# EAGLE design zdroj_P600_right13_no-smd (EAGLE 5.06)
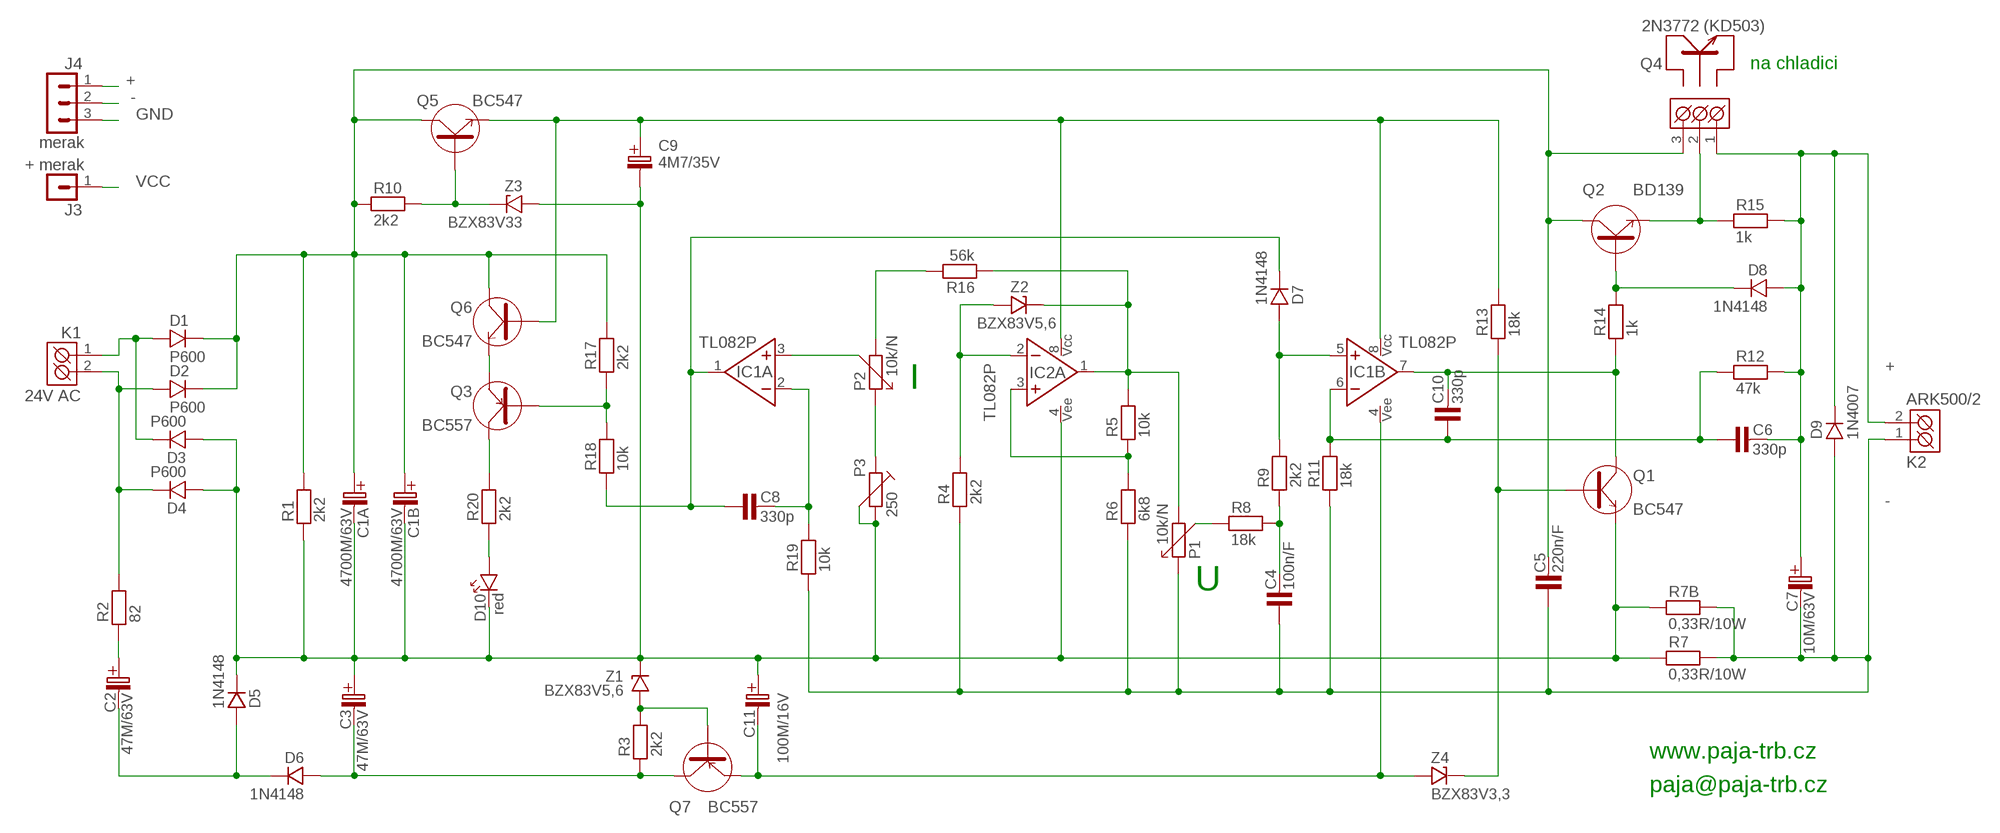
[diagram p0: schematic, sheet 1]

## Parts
C1A  4700M/63V  [C_EL12,5]
C1B  4700M/63V  [C_EL12,5]
C2  47M/63V  [C_EL_3,5]
C3  47M/63V  [C_EL_3,5]
C4  100n/F  100N-K/100  [RM5_3,2]
C5  220n/F  220N-K/63V  [RM5_3,2]
C6  330p  C-KERAMIK_2,5  [C-2,5]
C7  10M/63V  [C_EL_2]
C8  330p  C-KERAMIK_2,5  [C-2,5]
C9  4M7/35V  4M7/50V  [C_EL_2]
C10  330p  C-KERAMIK_2,5  [C-2,5]
C11  100M/16V  [C_EL_2,5]
D1  P600  D_P6  [P6]
D2  P600  D_P6  [P6]
D3  P600  D_P6  [P6]
D4  P600  D_P6  [P6]
D5  1N4148  1N4148_7,5  [DO35]
D6  1N4148  1N4148_7,5  [DO35]
D7  1N4148  1N4148_7,5  [DO35]
D8  1N4148  1N4148_7,5  [DO35]
D9  1N4007  1N4007_10  [DO41]
D10  red  LED_5  [LED_5]
IC1  TL082P  TL072  [DIL8]
IC2  TL082P  TL072  [DIL8]
J3  + merak  S1G1_JUMP  [S1G1_JUM]
J4  merak  S1G3_JUMP  [S1G3_JUM]
K1  24V AC  ARK500/2  [ARK500/2]
K2  ARK500/2  [ARK500/2]
P1  10k/N  PC16ML"  [PC16ML]
P2  10k/N  PC16ML"  [PC16ML]
P3  250  TRIMRPT6V  [PT6V]
Q1  BC547  BC546  [TO-92]
Q2  BD139  BD139_STOJ  [TO-126S]
Q3  BC557  BC556  [TO-92]
Q4  2N3772 (KD503)  ARK500/3  [ARK500/3]
Q5  BC547  BC546  [TO-92]
Q6  BC547  BC546  [TO-92]
Q7  BC557  BC556  [TO-92]
R1  2k2  W2_2K2  [R__2W]
R2  82  R_7,5  [R-7,5]
R3  2k2  R_7,5  [R-7,5]
R4  2k2  R_7,5  [R-7,5]
R5  10k  R_7,5  [R-7,5]
R6  6k8  R_7,5  [R-7,5]
R7  0,33R/10W  R__10W  [R-_10W]
R7B  0,33R/10W  R__10W  [R-_10W]
R8  18k  R_7,5  [R-7,5]
R9  2k2  R_7,5  [R-7,5]
R10  2k2  R_7,5  [R-7,5]
R11  18k  R_7,5  [R-7,5]
R12  47k  R_7,5  [R-7,5]
R13  18k  R_7,5  [R-7,5]
R14  1k  R_7,5  [R-7,5]
R15  1k  R_7,5  [R-7,5]
R16  56k  R_7,5  [R-7,5]
R17  2k2  R_7,5  [R-7,5]
R18  10k  R_7,5  [R-7,5]
R19  10k  R_7,5  [R-7,5]
R20  2k2  R_7,5  [R-7,5]
Z1  BZX83V5,6  D-ZENEROVA_0,5W_BZX83V  [DO35]
Z2  BZX83V5,6  D-ZENEROVA_0,5W_BZX83V  [DO35]
Z3  BZX83V33  D-ZENEROVA_0,5W_BZX83V  [DO35]
Z4  BZX83V3,3  D-ZENEROVA_2W_BZY  [DO41]

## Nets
+: C6.2 C7.C+(C_EL+) D8.A D9.K J4.1 K2.2(K2) Q4.1(K1) R12.2 R15.2
-: C4.1 C5.1 C7.C-(C_EL-) D9.A J4.2 K2.1(K1) P1.1 R4.1 R6.1 R7.2 R7B.2 R11.1 R19.1
GND: C1A.C-(C_EL-) C1B.C-(C_EL-) C3.C+(C_EL+) C9.C-(C_EL-) C11.C+(C_EL+) D3.A D4.A D5.K D10.K IC2.4(NS:VEE) J4.3 P3.2 P3.3 Q1.3(E) R1.1 R7.1 R7B.1 Z1.K Z3.A
N$2: Q3.1(C) R20.2
N$3: C2.C+(C_EL+) R2.1
N$5: C2.C-(C_EL-) D5.A D6.K
N$6: C3.C-(C_EL-) D6.A Q7.1(C) R3.1
N$8: C11.C-(C_EL-) IC1.4(NS:VEE) Q7.3(E) Z4.A
N$9: C8.1 D7.K IC1.1(A:VYSTUP) R18.1
N$10: IC1.3(A:NEIN+) P2.3
N$11: Q5.2(B) R10.2 Z3.K
N$12: D10.A R20.1
N$13: Q3.3(E) Q6.3(E)
N$14: P1.3 R8.1
N$15: Q3.2(B) R17.1 R18.2
N$17: C9.C+(C_EL+) IC1.8(NS:VCC) IC2.8(NS:VCC) Q5.3(E) Q6.2(B) R13.2
N$18: C8.2 IC1.2(A:IN-) R19.2
N$19: P2.1 P3.1
N$22: IC2.2(A:IN-) R4.2 Z2.A
N$23: IC2.3(A:NEIN+) R5.1 R6.2
N$24: IC2.1(A:VYSTUP) P1.2 R5.2 R16.1 Z2.K
N$25: P2.2 R16.2
N$27: C4.2 R8.2 R9.1
N$28: D7.A IC1.5(B:NEIN+) R9.2
N$29: C6.1 C10.1 IC1.6(B:IN-) R11.2 R12.1
N$31: C10.2 IC1.7(B:VYSTUP) Q1.1(C) R14.1
N$32: Q1.2(B) R13.1 Z4.K
N$33: Q2.1(E) Q4.2(K2) R15.1
N$36: D8.K Q2.3(B) R14.2
STRID1: D1.A D3.K K1.1(K1)
STRID2: D2.A D4.K K1.2(K2) R2.2
VCC: C1A.C+(C_EL+) C1B.C+(C_EL+) C5.2 D1.K D2.K J3.1 Q2.2(C) Q4.3(K3) Q5.1(C) Q6.1(C) R1.2 R10.1 R17.2
Z1: Q7.2(B) R3.2 Z1.A
Unconnected: IC2.5(B:NEIN+) IC2.6(B:IN-) IC2.7(B:VYSTUP)

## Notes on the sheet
- na chladici
- I
- U
- www.paja-trb.cz
- paja@paja-trb.cz

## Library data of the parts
C1A C1B = #PaJa_C-el_2:4700M/63V
C2 C3 = #PaJa_C-el_2:47M/63V
C4 = #PaJa_C-folie:100N-K/100
C5 = #PaJa_C-folie:220N-K/63V
C6 C8 C10 = #PaJa_22:C-KERAMIK: Kondenzator - keramicky
C7 = #PaJa_C-el_2:10M/63V
C9 = #PaJa_C-el_2:4M7/50V
C11 = #PaJa_C-el_2:100M/16V
D1-D4 = #PaJa_23_e56:D: Dioda - univerzální
D5-D8 = #PaJa_23_e56:1N4148: Univerzalni dioda - 0,15A, 75V
D9 = #PaJa_23_e56:1N4007: Usmernovaci dioda - 1A, 1000V
D10 = #PaJa_23_e56:LED: LED - jednobarevna
IC1 IC2 = #PaJa_23_e56:TL072: OZ - JFET - 2x
J3 = #PaJa_23_e56:S1G1_JUMP: Radove konektory - koliky - 1x
J4 = #PaJa_23_e56:S1G3_JUMP: Radove konektory - koliky - 3x
K1 K2 = #PaJa_23_e56:ARK500/2: Svorkovnice - roztec 5mm - dvojita
P1 P2 = #PaJa_23_e56:PC16ML: Potenciometr - plastovy - mono - 100R az 5M
P3 = #PaJa_22:TRIMR: Trimr
Q1 Q5 Q6 = #PaJa_23_e56:BC546: Tranzistor NPN - Univerzalni NF - Ic=0,1A
Q2 = #PaJa_23_e56:BD139: Tranzistor NPN - Vykonovy - Ic=1,5A
Q3 Q7 = #PaJa_23_e56:BC556: Tranzistor PNP - Univerzalni NF - Ic=0,1A
Q4 = #PaJa_23_e56:ARK500/3: Svorkovnice - roztec 5mm - trojita
R1 = #PaJa_R:W2_2K2
R2 R3 R7 R7B R9-R12 R14 R15 R17 R18 = #PaJa_23_e56:R: Rezistor
R4-R6 R8 R13 R16 R19 R20 = #PaJa_22:R: Rezistor
Z1-Z4 = #PaJa_23_e56:D-ZENEROVA: Zenerova dioda

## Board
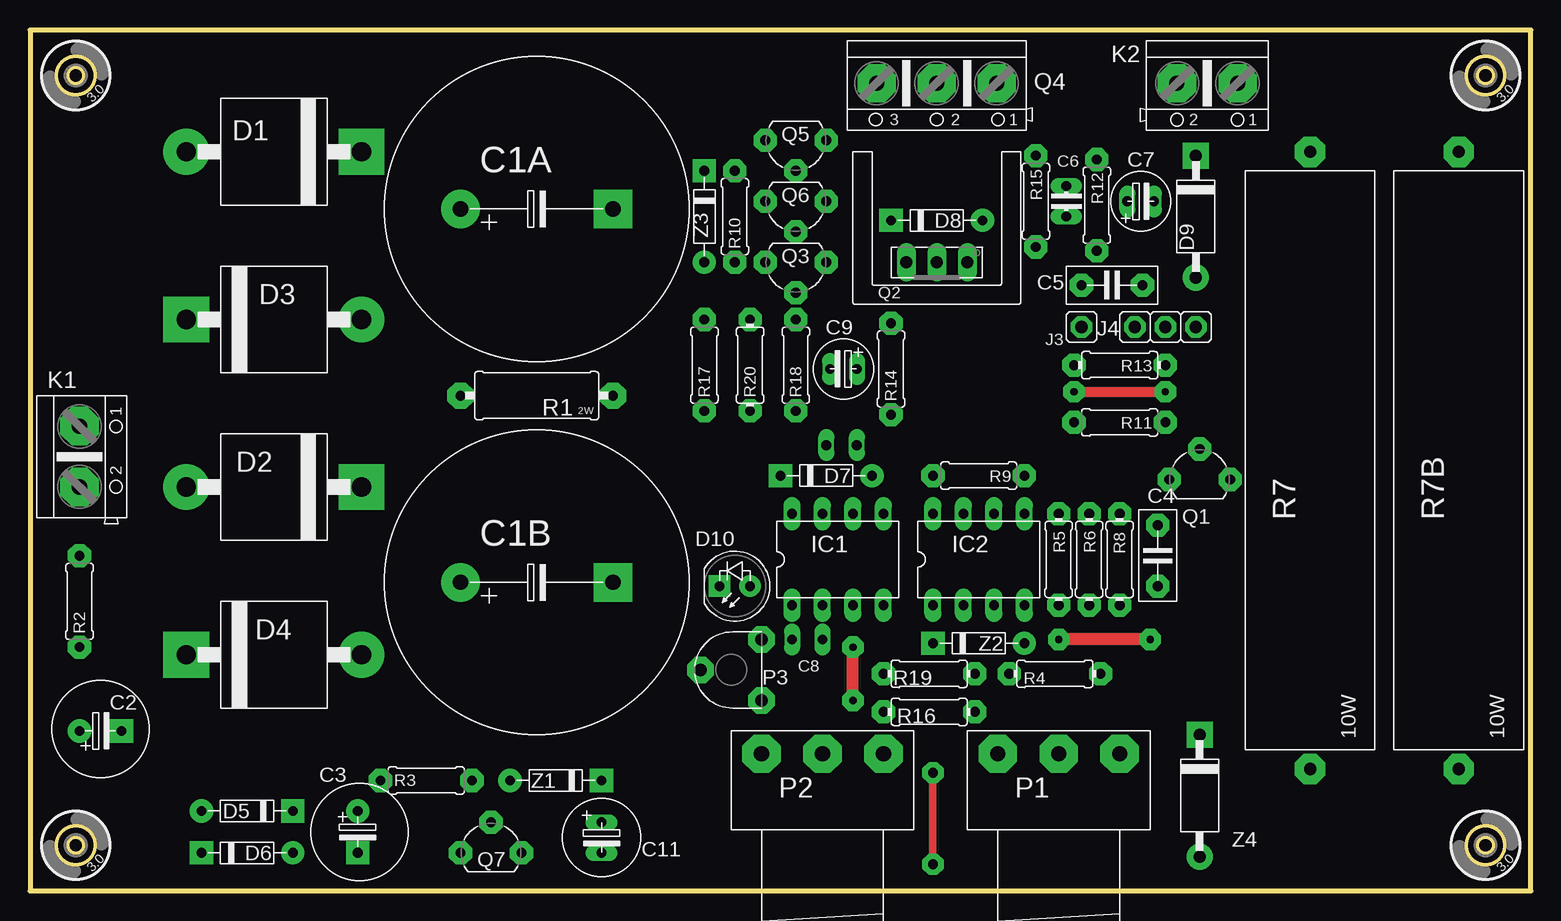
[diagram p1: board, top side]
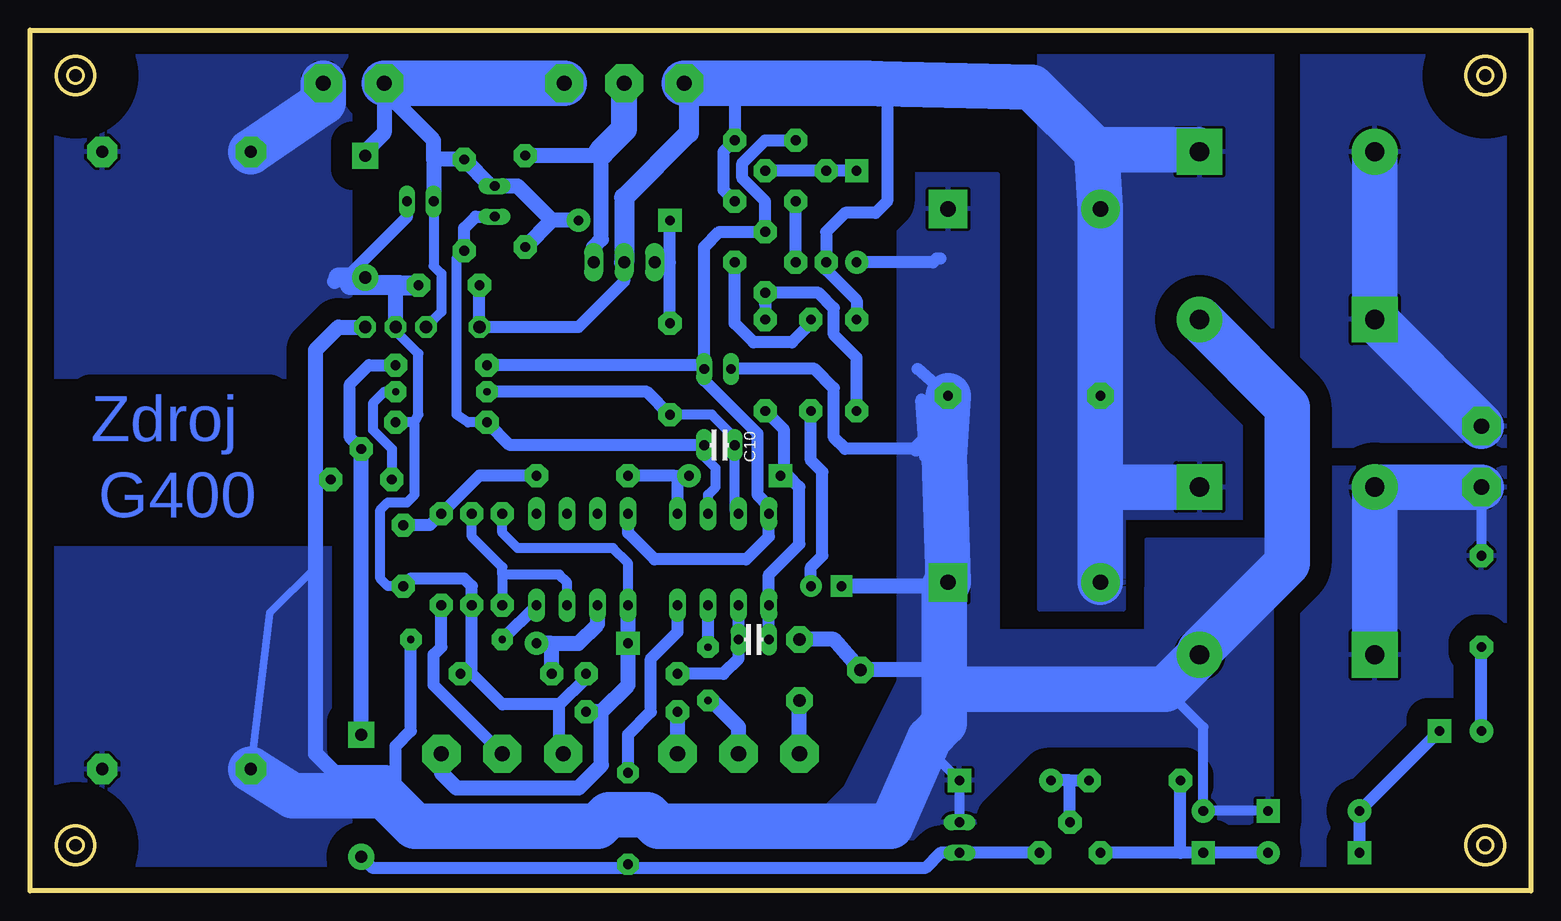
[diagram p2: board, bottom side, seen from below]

Size 125.08 x 71.75 mm. Coordinates in mm from the lower left corner, seen from the top.
Outline: 0,0 125.08,0 125.08,71.75 0,71.75 0,0
Copper layers (1*16): Top 0.035mm / dielectric 1.5mm / Bottom 0.035mm
Design rules "default": minimum track width 10mil, minimum drill 24mil, track to track 8mil, track to pad 8mil, pad to pad 8mil, via to via 8mil, smd to smd 8mil, copper to edge 40mil, drill to drill 8mil, minimum pad ring 10mil, minimum via ring 8mil, stop-mask expansion 4mil, vias tented up to drill 0mil, thermal gap 10mil
bRestrict: 2 lines

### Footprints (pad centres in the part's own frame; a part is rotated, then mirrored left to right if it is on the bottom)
C_EL12,5 = drill 1.27 pad 3.2 round: C+ -6.35,0 | drill 1.27 pad 3.2 square: C- 6.35,0
C_EL_3,5 = drill 0.813 pad 1.93 round: C+ 0,0 | drill 0.813 pad 1.93 square: C- 3.493,0
RM5_3,2 = drill 0.813 pad 1.93 octagon: 1 -2.54,0; 2 2.54,0
C-2,5 = drill 0.813 pad 1.27 long: 1 -1.27,0; 2 1.27,0
C_EL_2 = drill 0.813 pad 1.27 long: C+ 0,0; C- 2.223,0
C_EL_2,5 = drill 0.813 pad 1.27 long: C+ -1.27,0; C- 1.27,0
P6 = drill 1.6 pad 3.81 round: A -7.303,0 | drill 1.6 pad 3.81 square: K 7.303,0
DO35 = drill 0.813 pad 1.93 round: A -3.81,0 | drill 0.813 pad 1.93 square: K 3.81,0
DO41 = drill 1.016 pad 2.184 round: A -5.08,0 | drill 1.016 pad 2.184 square: K 5.08,0
LED_5 = drill 0.813 pad 1.778 round: A -1.27,0 | drill 0.813 pad 1.778 square: K 1.27,0
DIL8 = drill 0.813 pad 1.4 long: 1 -3.81,-3.81; 2 -1.27,-3.81; 3 1.27,-3.81; 4 3.81,-3.81; 5 3.81,3.81; 6 1.27,3.81; 7 -1.27,3.81; 8 -3.81,3.81
S1G1_JUM = drill 1.016 pad 1.778 octagon: 1 0,0
S1G3_JUM = drill 1.016 pad 1.778 octagon: 1 -2.54,0; 2 0,0; 3 2.54,0
ARK500/2 = drill 1.27 pad 3.2 octagon: 1 -2.54,0; 2 2.54,0
PC16ML = drill 1.27 pad 3.2 octagon: 1 -5.08,0; 2 5.08,0; 3 0,0
PT6V = drill 1.016 pad 2.184 octagon: 1 -2.54,-2.54; 2 0,2.54; 3 2.54,-2.54
TO-92 = drill 0.813 pad 1.93 octagon: 1 0,2.54; 2 2.54,0; 3 0,-2.54
TO-126S = drill 1.016 pad 1.6 long: 1 -2.54,0; 2 0,0; 3 2.54,0
ARK500/3 = drill 1.27 pad 3.2 octagon: 1 -5,0; 2 0,0; 3 5,0
R__2W = drill 0.813 pad 2.184 octagon: 1 -6.35,0; 2 6.35,0
R-7,5 = drill 0.813 pad 1.93 octagon: 1 -3.81,0; 2 3.81,0
R-_10W = drill 1.016 pad 2.54 octagon: 1 -25.718,0; 2 25.718,0
HOLE_3,0 = hole 3.2: 0,0

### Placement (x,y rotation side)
C1A  42.23,56.83 0 top
C1B  42.23,25.72 0 top
C2  4.13,13.34 0 top
C3  27.3,6.67 270 top
C4  93.98,27.94 90 top
C5  90.17,50.48 180 top
C6  86.36,57.47 90 top
C7  91.44,57.47 0 top
C8  64.77,20.95 180 bottom
C9  68.9,43.5 180 top
C10  67.63,37.15 0 bottom
C11  47.62,4.45 270 top
CHLAD  [CH_DO1_S]  75.56,48.9 180 top
D1  20.32,61.59 0 top
D2  20.32,33.66 0 top
D3  20.32,47.62 180 top
D4  20.32,19.68 180 top
D5  18.1,6.67 0 top
D6  18.1,3.17 180 top
D7  66.36,34.61 180 top
D8  75.56,55.88 180 top
D9  97.16,56.2 90 top
D10  58.74,25.4 180 top
IC1  67.31,27.62 0 top
IC2  79.06,27.62 0 top
J3  87.63,46.99 0 top
J4  94.61,46.99 0 top
K1  4.13,36.2 270 top
K2  98.11,67.31 180 top
P1  85.73,11.43 0 top
P2  66.04,11.43 0 top
P3  58.42,18.41 90 top
Q1  97.47,34.29 90 top
Q2  75.56,52.39 180 top
Q3  63.82,52.39 270 top
Q4  75.56,67.31 180 top
Q5  63.82,62.55 270 top
Q6  63.82,57.47 270 top
Q7  38.42,3.17 90 top
R1  42.23,41.27 180 top
R2  4.13,24.13 90 top
R3  33.02,9.21 0 top
R4  85.41,18.1 180 top
R5  85.73,27.62 90 top
R6  88.27,27.62 90 top
R7  106.68,35.88 90 top
R7B  119.06,35.88 90 top
R8  90.81,27.62 90 top
R9  79.06,34.61 180 top
R10  58.74,56.2 90 top
R11  90.81,39.05 180 top
R12  88.9,57.15 90 top
R13  90.81,43.81 180 top
R14  71.75,43.5 90 top
R15  83.82,57.47 270 top
R16  74.93,14.92 180 top
R17  56.2,43.81 90 top
R18  63.82,43.81 90 top
R19  74.93,18.1 180 top
R20  60.01,43.81 90 top
U$1  [HOLE_3,0]  121.28,67.94 0 top
U$2  [HOLE_3,0]  121.28,3.81 0 top
U$3  [HOLE_3,0]  3.81,3.81 0 top
U$4  [HOLE_3,0]  3.81,67.94 0 top
Z1  43.81,9.21 0 top
Z2  79.06,20.64 180 top
Z3  56.2,56.2 90 top
Z4  97.47,7.94 90 top

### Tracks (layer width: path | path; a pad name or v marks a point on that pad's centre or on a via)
+
  Bottom 0.813: C7.C+ 91.44,52.07 90.81,51.44 90.81,48.26 J4.1
  Bottom 1.016: R12.2 88.58,60.96
  Bottom 1.27: 91.44,60.96 C7.C+ | 91.44,60.96 R12.2 86.68,58.74 C6.2 84.45,58.74 81.6,55.88 | D9.K 97.15,61.59 95.57,63.18 95.57,66.67 | 95.57,66.67 K2.2 | 91.44,60.96 91.44,62.55 95.57,66.67 | D8.A 81.6,55.88 | 81.6,55.88 R15.2
  Bottom 3.81: K2.2 Q4.1
-
  Bottom 0.813: 94.93,46.99 92.71,44.77 92.71,39.69 93.03,39.05 | 93.03,39.05 R11.1 | 93.03,39.05 93.03,33.02 93.66,32.38 95.25,32.38 95.89,31.75 95.89,26.04 95.25,25.4 C4.1
  Bottom 1.016: 80.96,15.56 80.96,11.75 P1.1 | C4.1 93.34,26.04 88.9,26.04 88.26,25.4 R6.1 88.26,18.1 | C7.C- 93.66,56.2 98.74,51.12 | 94.93,46.99 J4.2 | 88.26,18.1 R4.1 | 88.26,18.1 85.73,15.56 80.96,15.56 | 80.96,15.56 78.74,17.78 R19.1
  Bottom 1.27: 99.38,51.12 99.7,50.8 | J4.2 94.61,50.16 94.3,50.48
  Bottom 1.676: C5.1 94.3,50.48 98.42,50.48 97.47,51.12 | 97.47,51.12 D9.A | 97.47,51.12 98.74,51.12 99.38,51.12
  Bottom 3.81: K2.1 100.65,65.72 R7.2
  pour Bottom (isolate 1.778): 124.14,71.12 98.42,71.12 98.42,42.86 124.14,42.86
GND  (via drill 0.6 pad 1.78)
  Top 1.016: v93.34,20.95 v85.73,20.95
  Bottom 0.61: 95.57,7.94 94.93,8.57 | 101.28,26.99 105.09,23.18 R7.1
  Bottom 0.813: D5.K C3.C+ 27.3,13.65 30.48,16.83 | C11.C+ Z1.K 50.8,12.38 50.48,12.7 50.17,12.7 | 95.25,9.84 94.61,9.21 95.25,8.89 94.93,8.57
  Bottom 1.016: v85.73,20.95 IC2.4 | v93.34,20.95 93.34,13.34 94.61,12.06 94.61,9.21 | 50.8,40.96 50.57,37.5 50.48,36.2 48.9,36.2 | Z3.A 49.85,52.39 49.53,52.7 49.21,52.7 | R1.1 51.12,43.5 | C9.C- 59.69,43.5 58.1,41.91 58.1,37.78 57.15,36.83 51.24,36.83
  Bottom 1.27: 50.48,9.84 51.75,10.16 | J4.3 99.38,46.99 101.28,45.09 101.28,34.29 | 95.25,9.84 99.7,9.84 101.28,11.43 101.28,34.29 | 101.28,34.29 Q1.3 | 48.9,25.4 D10.K | 48.9,18.41 P3.2 58.1,20.95 P3.3 | 50.57,37.5 51.24,36.83
  Bottom 3.81: R1.1 48.9,36.2 C1B.C- 48.9,25.4 48.9,18.41 48.9,16.83 | R7.1 103.19,7.94 95.57,7.94 93.03,5.4 77.79,5.4 76.83,6.35 73.66,6.35 72.71,5.4 53.34,5.4 50.17,12.7 48.9,13.97 48.9,16.83 | 48.9,16.83 30.48,16.83 D4.A 27.62,20 20.32,27.3 20.32,40.32 D3.A
  pour Bottom (isolate 1.778): 21.59,0 21.59,29.21 32.07,29.21 32.07,21.59 44.45,21.59 44.45,59.69 52.7,59.69 52.7,17.46 57.15,8.57 58.74,6.99 58.74,0.32
  pour Bottom (isolate 1.778): 125.09,0.32 125.09,28.57 98.42,28.57 98.42,0.32
N$2
  Bottom 1.016: R20.2 60.01,47.31 61.59,45.72 64.77,45.72 66.36,47.31 Q3.1
N$3
  Bottom 1.016: C2.C+ R2.1
N$5
  Bottom 1.016: C2.C- D5.A D6.K
N$6
  Bottom 1.016: D6.A C3.C- 29.21,3.17 | 29.21,3.17 Q7.1 | 29.21,3.17 R3.1
N$8  (via drill 0.81 pad 1.78)
  Top 0.61: v75.25,2.22 v75.25,9.84
  Bottom 1.016: IC1.4 71.12,21.59 73.34,19.37 73.34,14.92 75.25,13.02 v75.25,9.84 | Z4.A 96.52,1.91 75.25,1.91 | 75.25,1.91 50.48,1.91 49.21,3.17 C11.C- Q7.3 | 75.25,1.91 v75.25,2.22
N$9
  Bottom 1.016: C8.1 IC1.1 63.5,26.35 60.96,28.89 60.96,33.66 61.91,34.61 D7.K 62.23,34.92 62.23,38.42 R18.1
N$10  (via drill 0.6 pad 1.78)
  Top 1.016: v68.58,15.88 v68.58,20.32
  Bottom 1.016: v68.58,20.32 IC1.3 | 68.26,15.88 v68.58,15.88
  Bottom 1.27: 68.26,15.88 66.04,13.65 P2.3
N$11
  Bottom 1.016: Q5.2 R10.2 Z3.K
N$12
  Bottom 1.016: D10.A 60.01,26.99 59.05,27.94 59.05,34.92 60.01,35.88 R20.1
N$13
  Bottom 1.016: Q3.3 Q6.3
N$14
  Bottom 1.016: P1.3 91.44,17.14 91.44,19.68 90.81,20.32 R8.1
N$15
  Bottom 1.016: R18.2 63.82,48.9 Q3.2 59.37,49.85 58.1,48.58 58.1,46.35 56.2,44.45 R17.1
N$17
  Bottom 1.016: IC2.8 75.25,29.84 73.02,27.62 65.4,27.62 63.5,29.53 IC1.8 63.5,32.07 64.45,33.02 64.45,38.1 68.9,42.55 C9.C+ | Q5.3 63.82,62.55 65.72,60.64 65.72,59.37 63.82,57.47 Q6.2 67.63,54.93 68.9,53.66 C9.C+ | R13.2 69.22,43.81 C9.C+
N$18
  Bottom 1.016: IC1.2 C8.2 66.04,19.37 67.31,18.1 R19.2
N$19
  Bottom 1.27: P2.1 P3.1
N$22
  Bottom 1.27: IC2.2 77.79,22.23 79.37,20.64 81.6,20.64 | 81.6,20.64 Z2.A | R4.2 81.6,20.64
N$23
  Bottom 0.813: IC2.3 80.33,25.72 80.96,26.35 85.73,26.35 | 85.73,26.35 85.73,26.99 88.26,29.53 R6.2 | 85.73,26.35 R5.1
N$24
  Bottom 0.813: IC2.1 75.25,27.3 76.52,28.57 84.45,28.57 85.73,29.84 R5.2
  Bottom 1.27: P1.2 90.81,9.84 89.53,8.57 79.37,8.57 77.47,10.48 77.47,14.92 | 77.47,14.92 R16.1 | IC2.1 Z2.K 75.25,17.14 77.47,14.92
N$25
  Bottom 1.27: P2.2 R16.2
N$27
  Bottom 1.016: C4.2 91.76,30.48 R8.2 87.63,34.61 R9.1
N$28
  Bottom 1.016: 71.44,34.61 D7.A | 71.44,34.61 R9.2 | IC1.5 71.12,34.29 71.44,34.61
N$29
  Bottom 0.813: R11.2 88.58,39.05 89.53,39.69 89.53,52.7 R12.1 | C10.1 68.9,36.2 67.94,35.24 67.94,33.66 68.58,33.02 IC1.6
  Bottom 1.016: C6.1 87.95,56.2 88.9,55.24 R12.1 | C10.1 85.09,37.15 R11.2 86.36,38.42
N$31  (via drill 0.6 pad 1.78)
  Top 0.813: v87,41.59 v94.61,41.59
  Bottom 0.813: v94.61,41.59 95.57,41.59 96.52,40.64 96.52,38.42 94.93,36.83 Q1.1 | IC1.7 66.36,31.75 C10.2 66.36,37.78 68.26,39.69 R14.1
  Bottom 1.016: v87,41.59 73.66,41.59 R14.1
N$32
  Bottom 1.016: R13.1 96.84,43.81 98.42,42.23 98.42,37.78 Q1.2
  Bottom 1.27: Z4.K Q1.2
N$33
  Bottom 1.27: Q2.1 78.11,53.66 77.47,54.29 77.47,61.28 | 77.47,61.28 77.47,61.59 | 77.47,61.28 R15.1
  Bottom 2.184: Q4.2 75.57,63.5 77.47,61.59
N$36
  Bottom 1.016: R14.2 71.76,52.39 | 71.76,52.39 D8.K | 71.76,52.39 Q2.3
STRID1
  Bottom 3.81: D1.A D3.K K1.1
  pour Bottom (isolate 1.778): 0,70.8 19.05,70.8 19.05,37.15 0,37.15
STRID2
  Bottom 0.813: K1.2 R2.2
  Bottom 3.81: K1.2 D2.A D4.K
  pour Bottom (isolate 1.778): 0,35.24 19.05,35.24 19.05,0 0,0
VCC
  Bottom 1.016: 66.36,67.31 Q5.1 67.31,61.59 67.31,58.42 Q6.1 | Q2.2 75.57,50.8 79.37,46.99 J3.1 C5.2 | R17.2 56.2,49.21 58.74,51.75 R10.1 58.74,54.93 57.15,56.52 54.61,56.52 53.66,57.47 53.66,67.27 54.29,67.28
  Bottom 1.27: 55.56,67.31 55.88,66.99 | 55.23,67.3 54.29,66.36
  Bottom 1.676: Q2.2 75.57,57.78 70.17,63.18 70.17,66.91 Q4.3
  Bottom 3.81: C1B.C+ 35.88,33.66 | 35.88,33.66 R1.2 C1A.C+ 36.19,61.59 36.35,61.75 | 36.35,61.75 41.59,66.99 54.29,67.28 55.23,67.3 55.56,67.31 66.36,67.31 Q4.3 | D1.K 27.78,61.75 36.35,61.75 | 35.88,33.66 D2.K
  pour Bottom (isolate 1.778): 21.59,70.8 21.59,31.11 33.97,31.11 33.97,23.5 40.96,23.5 40.96,70.8
Z1
  Bottom 1.016: 38.42,9.21 R3.2 | 38.42,9.21 Z1.A | Q7.2 38.42,9.21

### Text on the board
Bottom: Zdroj | G400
